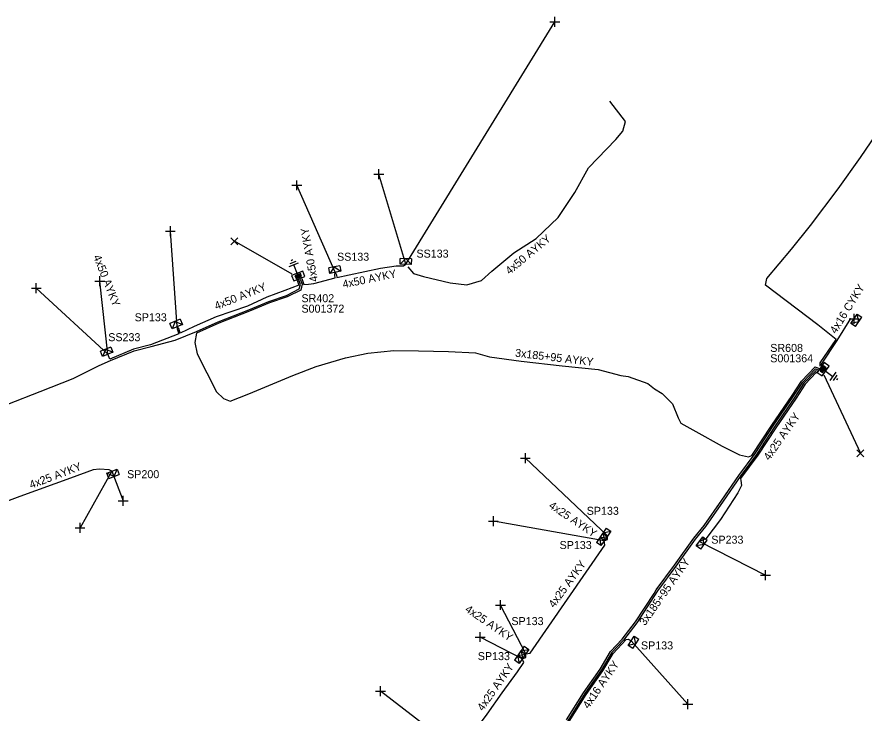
# Model space of a CAD drawing. Extents: x -763093 to -760976, y -1155572 to -1152009.
# Drawn here: x -761685 to -761579.1, y -1155172.9 to -1155085.8 of the extents above; entities that cross this region are included whole.
import ezdxf

# ---------------------------------------------------------------- set-up
doc = ezdxf.new("R2010")
doc.units = 0
for name, color, linetype in [('Vrstva 1', 7, 'Continuous'), ('Vrstva 14', 7, 'Continuous'), ('Vrstva 15', 7, 'Continuous'), ('Vrstva 28', 7, 'Continuous'), ('Vrstva 29', 7, 'Continuous'), ('Vrstva 30', 7, 'Continuous'), ('Vrstva 31', 7, 'Continuous'), ('Vrstva 33', 7, 'Continuous'), ('Vrstva 34', 7, 'Continuous'), ('Vrstva 5', 7, 'Continuous'), ('Vrstva 52', 7, 'Continuous'), ('Vrstva 54', 7, 'Continuous'), ('Vrstva 59', 7, 'Continuous'), ('Vrstva 6', 7, 'Continuous'), ('Vrstva 8', 7, 'Continuous'), ('Vrstva 9', 7, 'Continuous')]:
    doc.layers.add(name, color=color, linetype=linetype)

# ---------------------------------------------------------------- blocks, each defined once
blk = doc.blocks.new('NN800')
at = {"layer": 'Vrstva 1'}
for points in [[(-0.44, 0.44), (0.44, -0.44)], [(-0.44, -0.44), (0.44, 0.44)]]:
    blk.add_lwpolyline(points, dxfattribs=at)
blk = doc.blocks.new('NN620')
at = {"layer": 'Vrstva 8'}
for points in [[(0.75, 0), (-0.75, 0)], [(-0.75, 0), (-0.75, -0.75)], [(0.75, -0.75), (0.75, 0)], [(-0.75, -0.75), (0.75, -0.75)], [(0.37, -0.18), (-0.38, -0.18)], [(-0.38, -0.18), (-0.38, -0.56)], [(-0.38, -0.56), (0.37, -0.56)], [(0.32, -0.23), (-0.33, -0.23)], [(-0.33, -0.23), (-0.33, -0.51)], [(-0.33, -0.51), (0.32, -0.51)], [(0.27, -0.27), (-0.28, -0.27)], [(-0.28, -0.27), (-0.28, -0.46)], [(-0.28, -0.46), (0.27, -0.46)], [(0.23, -0.32), (-0.23, -0.32)], [(-0.23, -0.32), (-0.23, -0.42)], [(-0.23, -0.42), (0.23, -0.42)], [(-0.19, -0.37), (0.19, -0.37)], [(0.23, -0.42), (0.23, -0.32)], [(0.27, -0.46), (0.27, -0.27)], [(0.32, -0.51), (0.32, -0.23)], [(0.37, -0.56), (0.37, -0.18)]]:
    blk.add_lwpolyline(points, dxfattribs=at)
blk = doc.blocks.new('NN630')
at = {"layer": 'Vrstva 9'}
for points in [[(0, -0.7), (-0.7, 0)], [(-0.7, -0.7), (-0.7, 0), (0.7, 0), (0.7, -0.7)], [(-0.7, -0.7), (0.7, -0.7)], [(0, -0.7), (0.7, 0)]]:
    blk.add_lwpolyline(points, dxfattribs=at)
blk = doc.blocks.new('NN810')
at = {"layer": 'Vrstva 14'}
for points in [[(0, -0.64), (0, -1.89)], [(0.63, -1.89), (-0.62, -1.89)], [(0.39, -2.2), (-0.4, -2.2)], [(0, -2.52), (-0.12, -2.52)], [(0.14, -2.52), (0, -2.52)]]:
    blk.add_lwpolyline(points, dxfattribs=at)

msp = doc.modelspace()

# ---------------------------------------------------------------- linework, layer by layer
at = {"layer": 'Vrstva 5'}
for points in [[(-761636.14, -1155117.06), (-761635.42, -1155117.9), (-761634.17, -1155118.29), (-761630.83, -1155119.07), (-761628.75, -1155119.34), (-761626.94, -1155118.79), (-761625.62, -1155117.63), (-761622.88, -1155115.31), (-761620.09, -1155113.52), (-761617.32, -1155110.92), (-761615.27, -1155107.77), (-761613.53, -1155104.71), (-761610.15, -1155101.15), (-761609.25, -1155100.09), (-761608.93, -1155098.88), (-761610.9, -1155096.37)], [(-761584.61, -1155129.5), (-761584.58, -1155129.06), (-761582.61, -1155126.15), (-761584.88, -1155124.31), (-761591.44, -1155119.38), (-761591.26, -1155118.52), (-761588.17, -1155114.87), (-761585.82, -1155111.9), (-761582.35, -1155107.33), (-761579.55, -1155103.39), (-761575.64, -1155097.65)], [(-761649.38, -1155118.54), (-761649.13, -1155119.27), (-761648.53, -1155119.26), (-761647.86, -1155119.14), (-761645.21, -1155118.44), (-761645.25, -1155118.1), (-761645.2, -1155117.76), (-761645.06, -1155118.07), (-761645.01, -1155118.39), (-761643.47, -1155118.06), (-761639.53, -1155117.23), (-761637.6, -1155116.95), (-761636.66, -1155116.93), (-761636.39, -1155116.75)], [(-761696.32, -1155137), (-761695.96, -1155137.15), (-761693.87, -1155136.93), (-761691.53, -1155136.37), (-761689.19, -1155135.6), (-761686.13, -1155134.23), (-761682.08, -1155132.66), (-761677.94, -1155131.03), (-761674.7, -1155129.42), (-761673.3, -1155128.79), (-761670.35, -1155127.58), (-761668.22, -1155127.03), (-761665.2, -1155126.24), (-761662.56, -1155125.16), (-761659.82, -1155123.93), (-761656, -1155122.45), (-761653.49, -1155121.4), (-761651.28, -1155120.66), (-761649.69, -1155119.84), (-761649.55, -1155119.28), (-761649.76, -1155118.68)], [(-761649.95, -1155118.74), (-761649.73, -1155119.38), (-761651.51, -1155120.04), (-761653.77, -1155120.85), (-761656.18, -1155121.98), (-761660.08, -1155123.33), (-761662.85, -1155124.55), (-761664.59, -1155125.36), (-761664.75, -1155124.78), (-761664.94, -1155124.55), (-761664.95, -1155124.84), (-761664.76, -1155125.44), (-761668.28, -1155126.83), (-761670.41, -1155127.38), (-761673.38, -1155128.61), (-761673.63, -1155128.01)], [(-761649.57, -1155118.61), (-761649.35, -1155119.26), (-761649.51, -1155119.98), (-761651.2, -1155120.84), (-761653.41, -1155121.58), (-761655.92, -1155122.63), (-761659.74, -1155124.11), (-761662.54, -1155125.37), (-761662.76, -1155126.54), (-761662.44, -1155127.94), (-761660.04, -1155132.69), (-761659.16, -1155133.55), (-761658.32, -1155133.87), (-761655.98, -1155132.97), (-761650.48, -1155130.64), (-761647.57, -1155129.54), (-761643.92, -1155128.46), (-761641.11, -1155127.85), (-761637.88, -1155127.54), (-761634.8, -1155127.58), (-761631.05, -1155127.65), (-761627.69, -1155127.84), (-761625.91, -1155128.34), (-761621.98, -1155128.85), (-761616.84, -1155129.46), (-761612.33, -1155129.92), (-761609.52, -1155130.64), (-761608.6, -1155130.77), (-761606.14, -1155131.65), (-761605.28, -1155132.32), (-761604.36, -1155132.93), (-761603.06, -1155134.21), (-761602.35, -1155135.94), (-761601.99, -1155136.64), (-761600.14, -1155137.67), (-761596.84, -1155139.48), (-761594.68, -1155140.59), (-761593.57, -1155140.84), (-761593.12, -1155140.67), (-761590.64, -1155136.85), (-761588.11, -1155133.16), (-761586.94, -1155131.35), (-761585.2, -1155129.56), (-761584.71, -1155129.79)], [(-761616.31, -1155173.72), (-761614.19, -1155170.33), (-761612.1, -1155167.36), (-761610.79, -1155165.19), (-761609.34, -1155163.62), (-761607.68, -1155161.46), (-761605.36, -1155157.9), (-761605.08, -1155157.46), (-761602.79, -1155154.39), (-761600.38, -1155151), (-761599.09, -1155149.41), (-761596.89, -1155146.24), (-761594.75, -1155143.16), (-761592.72, -1155140.43), (-761590.47, -1155136.96), (-761587.93, -1155133.26), (-761586.78, -1155131.48), (-761585.18, -1155129.82), (-761584.84, -1155129.94)], [(-761584.97, -1155130.11), (-761585.14, -1155130.06), (-761586.62, -1155131.6), (-761587.78, -1155133.39), (-761590.31, -1155137.08), (-761592.56, -1155140.53), (-761594.59, -1155143.27), (-761596.73, -1155146.36), (-761598.93, -1155149.53), (-761600.22, -1155151.12), (-761602.63, -1155154.51), (-761604.92, -1155157.58), (-761607.52, -1155161.58), (-761609.19, -1155163.76), (-761610.63, -1155165.31), (-761611.93, -1155167.47), (-761614.02, -1155170.44), (-761616.14, -1155173.83), (-761618.04, -1155176.77), (-761620.3, -1155180.1), (-761622.77, -1155183.58), (-761624.38, -1155185.85), (-761624.56, -1155186.62), (-761624.53, -1155187.36)], [(-761673.11, -1155142.63), (-761673.44, -1155142.47), (-761674.65, -1155142.38), (-761675.45, -1155142.44), (-761678.27, -1155143.5), (-761684.62, -1155145.77), (-761689.68, -1155147.68), (-761690.24, -1155147.66), (-761690.88, -1155146.97), (-761691.58, -1155145.85), (-761693.37, -1155140.12), (-761693.63, -1155139.43), (-761693.89, -1155139.3), (-761695.59, -1155139.37), (-761696.12, -1155139.05), (-761696.6, -1155137.57), (-761696.87, -1155137.24)], [(-761630.28, -1155178.3), (-761629.96, -1155178.53), (-761629.66, -1155177.89), (-761628.37, -1155175.94), (-761626.22, -1155173.02), (-761624.33, -1155170.35), (-761622.41, -1155167.72), (-761621.65, -1155166.55), (-761621.83, -1155166.08), (-761621.4, -1155165.91), (-761621.4, -1155165.48), (-761620.85, -1155165.36), (-761611.49, -1155151.86), (-761611.59, -1155151.35), (-761611.19, -1155151.16), (-761611.16, -1155150.72)], [(-761624.36, -1155187.16), (-761624.38, -1155186.65), (-761624.22, -1155185.97), (-761622.61, -1155183.7), (-761620.16, -1155180.25), (-761617.87, -1155176.88), (-761615.97, -1155173.94), (-761613.85, -1155170.55), (-761611.76, -1155167.58), (-761610.47, -1155165.43), (-761608.85, -1155163.68), (-761608.6, -1155163.63), (-761608.21, -1155163.82)]]:
    msp.add_lwpolyline(points, dxfattribs=at)
at = {"layer": 'Vrstva 52'}
for points in [[(-761584.43, -1155129.41), (-761584.44, -1155129.25), (-761582.46, -1155126.3), (-761580.75, -1155123.53), (-761580.36, -1155123.57)], [(-761584.97, -1155130.35), (-761585.09, -1155130.3), (-761586.46, -1155131.73), (-761587.61, -1155133.5), (-761590.14, -1155137.19), (-761592.39, -1155140.64), (-761594.54, -1155143.54), (-761594.5, -1155143.8), (-761594.42, -1155144.42), (-761594.9, -1155145.32), (-761597.03, -1155148.65), (-761598.89, -1155151.07), (-761599.68, -1155151.4)]]:
    msp.add_lwpolyline(points, dxfattribs=at)
at = {"layer": 'Vrstva 59'}
for points in [[(-761636.39, -1155116.75), (-761617.76, -1155086.45)], [(-761636.39, -1155116.75), (-761639.75, -1155105.5)], [(-761645.2, -1155117.76), (-761650, -1155106.88)], [(-761664.94, -1155124.55), (-761665.81, -1155112.63)], [(-761650.59, -1155117.98), (-761657.81, -1155113.88)], [(-761673.63, -1155128.01), (-761674.63, -1155118.88)], [(-761673.63, -1155128.01), (-761682.56, -1155119.75)], [(-761584.15, -1155130.57), (-761579.56, -1155140.38)], [(-761611.16, -1155150.72), (-761621.44, -1155141)], [(-761673.11, -1155142.63), (-761677.1, -1155149.7)], [(-761673.11, -1155142.63), (-761671.72, -1155146.32)], [(-761611.59, -1155151.35), (-761625.44, -1155148.88)], [(-761599.68, -1155151.4), (-761591.44, -1155155.63)], [(-761621.4, -1155165.48), (-761624.56, -1155159.36)], [(-761621.83, -1155166.08), (-761627.08, -1155163.36)], [(-761608.21, -1155163.82), (-761601.13, -1155171.75)], [(-761629.86, -1155177.6), (-761639.56, -1155170.13)]]:
    msp.add_lwpolyline(points, dxfattribs=at)

# ---------------------------------------------------------------- block references
at = {"layer": 'Vrstva 15'}
for p, rotation in [((-761649.69, -1155118.57), -159.01991673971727), ((-761584.53, -1155129.66), 54.00960379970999)]:
    msp.add_blockref('NN810', p, dxfattribs=dict(at, rotation=rotation))
at = {"layer": 'Vrstva 28'}
for p, rotation in [((-761649.69, -1155118.57), -158.6009917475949), ((-761584.53, -1155129.66), 54.009603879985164)]:
    msp.add_blockref('NN620', p, dxfattribs=dict(at, rotation=rotation))
at = {"layer": 'Vrstva 31'}
for p, rotation in [((-761636.39, -1155116.75), 179.1064694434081), ((-761645.2, -1155117.76), -169.0475075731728), ((-761664.94, -1155124.55), -157.10706025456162), ((-761580.36, -1155123.57), 56.600009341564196), ((-761673.63, -1155128.01), -158.56750272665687), ((-761673.11, -1155142.63), 21.801408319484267), ((-761611.16, -1155150.72), -124.58662498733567), ((-761611.59, -1155151.35), -124.57419171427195), ((-761599.68, -1155151.4), 54.60707199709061), ((-761608.21, -1155163.82), 56.63116345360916), ((-761621.4, -1155165.48), -124.8563221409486), ((-761621.83, -1155166.08), -124.76765832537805)]:
    msp.add_blockref('NN630', p, dxfattribs=dict(at, rotation=rotation))
at = {"layer": 'Vrstva 34'}
for p, rotation in [((-761617.76, -1155086.45), 45.00000009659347), ((-761639.75, -1155105.5), 45), ((-761650, -1155106.88), 45), ((-761665.81, -1155112.63), 45), ((-761674.63, -1155118.88), 45), ((-761682.56, -1155119.75), 45), ((-761580.36, -1155123.57), 45), ((-761621.44, -1155141), 44.99999995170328), ((-761671.72, -1155146.32), 45), ((-761677.1, -1155149.7), 45.00000009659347), ((-761625.44, -1155148.88), 44.99999995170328), ((-761591.44, -1155155.63), 44.99999995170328), ((-761624.56, -1155159.36), 45), ((-761627.08, -1155163.36), 44.99999995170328), ((-761639.56, -1155170.13), 45), ((-761601.13, -1155171.75), 45)]:
    msp.add_blockref('NN800', p, dxfattribs=dict(at, rotation=rotation))
for p in [(-761657.81, -1155113.88), (-761579.56, -1155140.38)]:
    msp.add_blockref('NN800', p, dxfattribs=at)

# ---------------------------------------------------------------- texts
at = {"layer": 'Vrstva 29'}
for s, p in [('S001372', (-761649.42, -1155122.8)), ('S001364', (-761590.83, -1155129.01))]:
    msp.add_text(s, height=1, dxfattribs=at).set_placement(p)
at = {"layer": 'Vrstva 30'}
for s, p in [('SR402', (-761649.42, -1155121.5)), ('SR608', (-761590.83, -1155127.71))]:
    msp.add_text(s, height=1, dxfattribs=at).set_placement(p)
at = {"layer": 'Vrstva 33'}
for s, p in [('SS133', (-761635.05, -1155115.92)), ('SS133', (-761644.97, -1155116.31)), ('SP133', (-761670.27, -1155123.88)), ('SS233', (-761673.57, -1155126.37)), ('SP200', (-761671.21, -1155143.5)), ('SP133', (-761613.77, -1155148.08)), ('SP233', (-761598.2, -1155151.69)), ('SP133', (-761617.16, -1155152.36)), ('SP133', (-761623.18, -1155161.87)), ('SP133', (-761606.99, -1155164.91)), ('SP133', (-761627.38, -1155166.25))]:
    msp.add_text(s, height=1, dxfattribs=at).set_placement(p)
at = {"layer": 'Vrstva 54'}
for s, rotation, p in [('4x16 CYKY', 58.313, (-761582.62, -1155125.52)), ('4x25 AYKY', 55.176, (-761590.95, -1155141.37))]:
    msp.add_text(s, height=1, rotation=rotation, dxfattribs=at).set_placement(p)
at = {"layer": 'Vrstva 6'}
for s, rotation, p in [('4x50 AYKY', 100.144, (-761647.36, -1155118.86)), ('4x50 AYKY', 39.768, (-761623.42, -1155118.1)), ('4x50 AYKY', 291.593, (-761675.47, -1155115.79)), ('4x50 AYKY', 11.694, (-761644.18, -1155119.75)), ('4x50 AYKY', 21.836, (-761660.06, -1155122.48)), ('3x185+95 AYKY', 353.229, (-761622.76, -1155128.3)), ('4x25 AYKY', 20.758, (-761683.21, -1155144.84)), ('4x25 AYKY', 326.094, (-761618.6, -1155147.14)), ('4x25 AYKY', 53.792, (-761617.84, -1155159.78)), ('3x185+95 AYKY', 54.837, (-761606.48, -1155162.02)), ('4x25 AYKY', 325.738, (-761629.07, -1155160.1)), ('4x25 AYKY', 55.029, (-761626.74, -1155172.7)), ('4x16 AYKY', 55.404, (-761613.54, -1155172.41))]:
    msp.add_text(s, height=1, rotation=rotation, dxfattribs=at).set_placement(p)

doc.saveas('drawing.dxf')
